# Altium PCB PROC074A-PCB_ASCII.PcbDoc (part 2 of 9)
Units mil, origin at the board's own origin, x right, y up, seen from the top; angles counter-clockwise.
Board outline 2755.91 x 5300 mil, 10 copper layers (Top Layer, L2-GND, L3-SIG1, L4-GND, L5-PWR/SIG, L6-SIG2, L7-PWR2, L8-SIG3, L9-GND, Bottom Layer), stack 67.57 mil thick; 586 components, 490 nets, 2137 pads, 1150 vias.
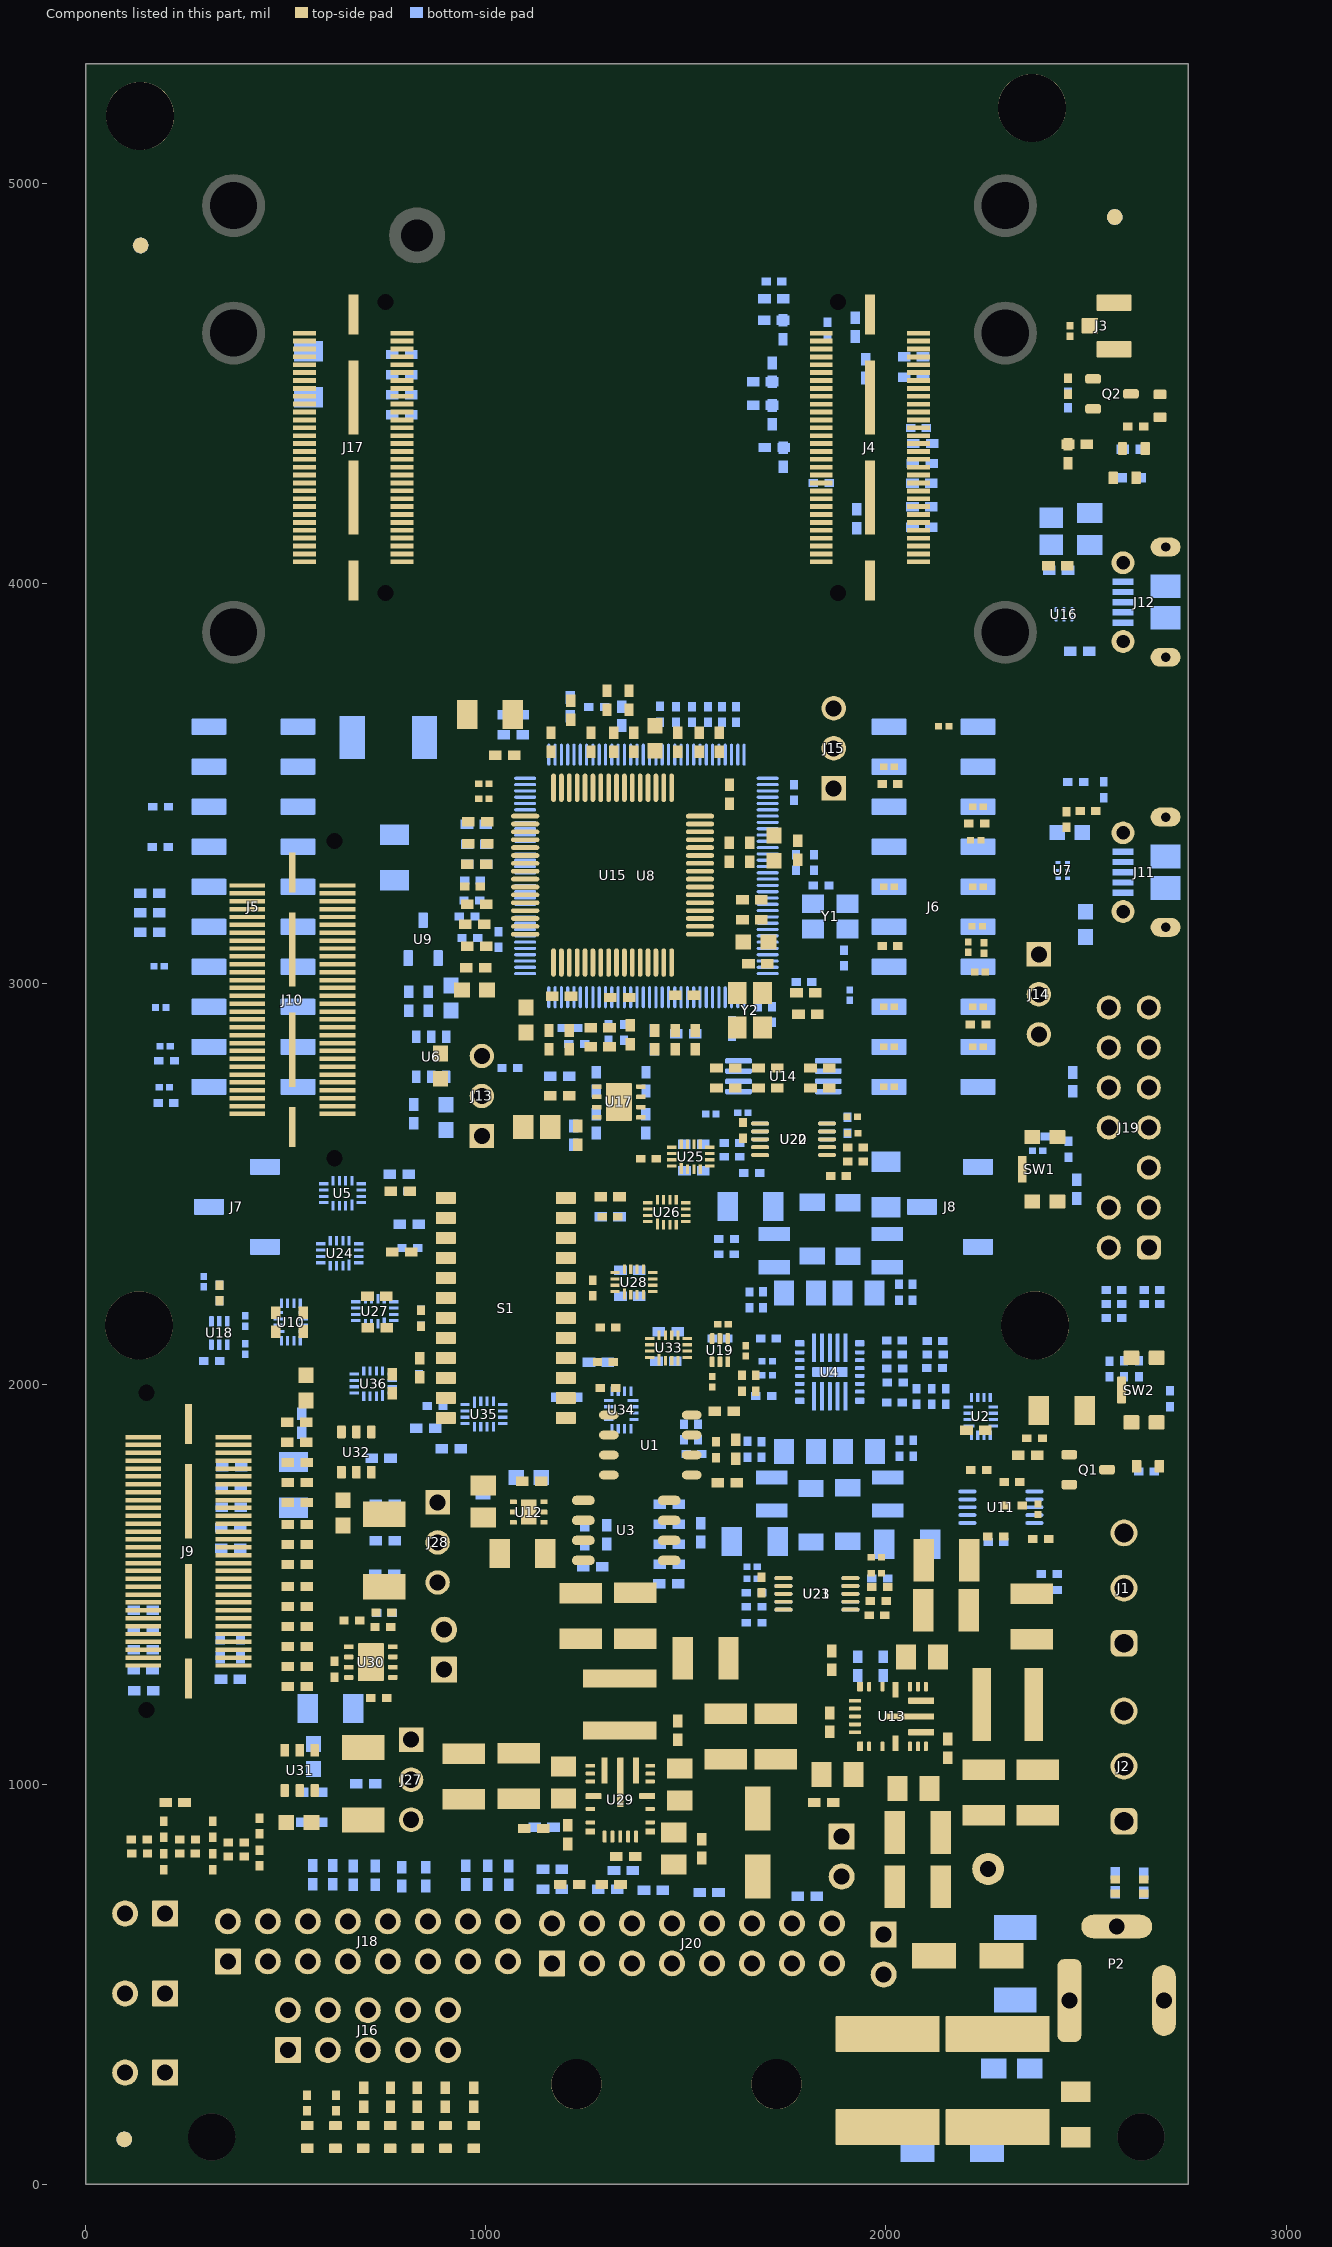
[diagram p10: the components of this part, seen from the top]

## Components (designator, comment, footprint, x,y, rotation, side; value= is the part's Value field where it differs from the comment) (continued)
R61 "CRCW040210K0FKED" 0402L 2010,3095 r0 top
R62 "CRCW04024K70JNED" 0402 1455.59,2130.24 r180 bottom
R63 "CRCW04024K70JNED" 0402 808.26,2399.95 r180 bottom
R64 "CRCW0402100KFKED" 0402L 2227,3401 r180 top
R65 "CRCW04024K70JNED" 0402 1201.75,1967.06 r0 bottom
R66 "CRCW04024K70JNED" 0402 1519.93,2599.87 r180 bottom
R67 "CRCW02010000Z0ED" 0201_Silk 2144.37,3644.06 r180 top
R68 "CRCW04024K70JNED" 0402 913.37,1838.06 r0 bottom
R69 "CRCW040210K0FKED" 0402 2090.01,4141.99 r180 bottom
R70 "CRCW02010000Z0ED" 0201_Silk 2007.63,3543 r0 top
R71 "CRCW040210K0FKED" 0402L 2570,2235 r0 bottom
R72 "CRCW02010000Z0ED" 0201_Silk 2230.07,3443 r0 top
R73 "CRCW0402100KFKED" 0402L 1720.37,4756.06 r180 bottom
R74 "ERJ-2GE0R00X" 0402L 2665,2200 r0 bottom
R75 "ERJ-2GE0R00X" 0402 160,3227 r180 bottom
R76 "CRCW02010000Z0ED" 0201_Silk 2224.37,3359.06 r0 top
R77 "CRCW02010000Z0ED" 0201_Silk 183.36,3044.06 r0 bottom
R78 "CRCW02010000Z0ED" 0201_Silk 2230.07,3243 r180 top
R79 "CRCW02010000Z0ED" 0201_Silk 187.38,2941.06 r0 bottom
R80 "ERJ-2GE0R00X" 0402L 2570,2200 r180 bottom
R81 "CRCW02010000Z0ED" 0201_Silk 2007.63,3243 r180 top
R82 "CRCW02010000Z0ED" 0201_Silk 198.37,2844.06 r0 bottom
R85 "CRCW02010000Z0ED" 0201_Silk 2228.36,3144.06 r180 top
R86 "CRCW02010000Z0ED" 0201_Silk 196.37,2742.06 r0 bottom
R88 "CRCW02010000Z0ED" 0201_Silk 1909.37,2972.05 r90 bottom
R89 "CRCW02010000Z0ED" 0201_Silk 2235,3030 r0 top
R90 "CRCW02010000Z0ED" 0201_Silk 2007.63,2943 r0 top
R91 "CRCW02010000Z0ED" 0201_Silk 2230.07,2943 r0 top
R92 "CRCW02010000Z0ED" 0201_Silk 2230.07,2843 r0 top
R93 "CRCW02010000Z0ED" 0201_Silk 2007.63,2843 r180 top
R94 "CRCW02010000Z0ED" 0201_Silk 2007.63,2743 r180 top
R95 "CRCW040210K0FKED" 0402L 2230.37,2899.06 r0 top
R96 "ERJ-2GE0R00X" 0402 362.62,1589.53 r180 bottom
R97 "CRCW04024K99FKED" 0402L 2021.27,2073.8 r0 bottom
R98 "CRCW04024K99FKED" 0402L 2023.27,2003.8 r0 bottom
R99 "CRCW02010000Z0ED" 0201_Silk 1703.26,2056.8 r180 bottom
R100 "CRCW02010000Z0ED" 0201_Silk 1703.26,2021.8 r180 bottom
R101 "CRCW04023R83FKED" 0402L 1692.69,2210.88 r90 bottom
R102 "CRCW04023R83FKED" 0402L 2032.22,2229.46 r90 bottom
R103 "CRCW04023R83FKED" 0402L 1689.22,1836.46 r270 bottom
R104 "CRCW04023R83FKED" 0402L 2034.22,1839.46 r270 bottom
R105 "ERJ-2GEJ102X" 0402L 2114.37,1969.06 r270 bottom
R106 "ERJ-2GE0R00X" 0402L 1601.72,2362.46 r0 bottom
R107 "ERJ-2RKF4991X" 0402L 2076.27,1968.8 r270 bottom
R108 "ERJ-2RKF4991X" 0402L 2123.37,2074.06 r180 bottom
R109 "CRCW040210K0FKED" 0402L 2149.37,1969.06 r90 bottom
R110 "CRCW040210K0FKED" 0402L 2121.68,2040.46 r180 bottom
R111 "CRCW0402100KFKED" 0402L 1601.41,2324.46 r0 bottom
R112 "CRCW04021K96FKED" 0402L 2122.37,2108.06 r180 bottom
R113 "CRCW20100000Z0EF" 2010 746.37,1584.06 r270 top
R114 "ERJ-2GEJ511X" 0402L 2651.37,1781.06 r180 bottom
R115 "CRCW20100000Z0EF" 2010 693,1001 r270 top
R116 "CRCW20100000Z0EF" 2010 2323,551 r90 bottom
R117 "ERJ-2GEJ511X" 0402L 2371.62,1864.53 r0 top
R118 "ERJ-2GEJ511X" 0402L 2624.37,4393.06 r180 top
R119 "ERJ-2GEJ101X" 0402L 2456,2587 r270 bottom
R120 "CRCW040210K0FKED" 0402L 2632.37,2038.06 r270 bottom
R121 "CRCW02010000Z0ED" 0201_Silk 2378.99,2583 r180 bottom
R122 "PMR18EZPFV2L00" 1206 1010.3,3673.44 r180 top
R123 "ERJ-2GEJ361X" 0402L 625.37,202.9 r90 top
R124 "ERJ-2GEJ101X" 0402L 2570,2165 r0 bottom
R125 "ERJ-2GEJ511X" 0402L 553,202.9 r90 top
R126 "CRCW040210K0FKED" 0402L 2379,2619 r0 bottom
R127 "ERJ-2GEJ101X" 0402L 2559,2037.68 r90 bottom
R128 "ERJ-2GEJ511X" 0402L 2455.37,4494.06 r90 top
R129 "ERJ-2GEJ101X" 0402L 2710,1963 r90 bottom
R130 "CRCW0402100KFKED" 0402L 2455,4460 r90 bottom
R131 "ERJ-2GE0R00X" 0402 223.06,954.08 r0 top
R132 "CRCW0402750RFKED" 0402L 134.54,826.26 r180 top
R133 "CRCW040210K0FKED" 0402L 194.68,887.05 r270 top
R134 "CRCW04027K87FKED" 0402L 194.68,805.99 r270 top
R135 "CRCW040282K5FKED" 0402L 133.54,861.27 r0 top
R136 "CRCW0402750RFKED" 0402L 254.54,861.27 r180 top
R137 "CRCW040210K0FKED" 0402L 254.37,826.26 r0 top
R138 "CRCW04027K87FKED" 0402L 317.18,805.99 r270 top
R139 "CRCW040282K5FKED" 0402L 317.18,887.05 r270 top
R140 "CRCW0402750RFKED" 0402L 434.59,895.45 r90 top
R141 "CRCW040210K0FKED" 0402L 375.81,853.64 r0 top
R142 "CRCW04027K87FKED" 0402L 434.59,815.45 r270 top
R143 "CRCW040282K5FKED" 0402L 375.81,818.64 r0 top
R144 "ERJ-2GE0R00X" 0402 527,1855 r180 top
R145 "ERJ-2GE0R00X" 0402 362.62,1640.53 r180 bottom locked
R146 "ERJ-2GE0R00X" 0402 363.87,1691.53 r180 bottom
R147 "RCS06030000Z0EA" 0603 886.91,2794.85 r90 top
R148 "CRCW0402510RJNED" 0402 856.1,2956.8 r270 bottom
R149 "ERJ-2RKF1003X" 0402 820,2675 r90 bottom
R150 "ERJ-2GE0R00X" 0402L 1059.92,2789.93 r180 bottom
R151 "CRCW040210K0FKED" 0402L 1406.35,2563.13 r180 top
R152 "CRCW0402330KFKED" 0402L 2451.11,3410.87 r270 top
R153 "CRCW040230K0FKED" 0402L 2544.37,3485.6 r270 bottom
R154 "MCT06030Z0000ZP500" 0603 2459.37,3378.62 r180 bottom
R155 "CRCW0402330KFKED" 0402L 2474.37,3505.06 r180 bottom
R156 "MCT06030Z0000ZP500" 0603 2498.62,3149.06 r90 bottom
R157 "ERJ-2GE0R00X" 0402 1068.37,3623.06 r0 bottom
R158 "ERJ-2GE0R00X" 0402L 1795,3005 r0 bottom
R159 "ERJ-2GEJ101X" 0402L 1680.49,2923.76 r270 bottom
R160 "ERJ-2GE0R00X" 0402 1068.37,3673.06 r0 bottom
R161 "CRCW02010000Z0ED" 0201_Silk 995,3463 r0 top
R162 "CRCW02010000Z0ED" 0201_Silk 995,3500 r0 top
R163 "CRCW04021K00FKED" 0402L 1625.49,3673.76 r90 bottom
R164 "CRCW04021K00FKED" 0402L 1590.49,3673.76 r90 bottom
R165 "CRCW04021K00FKED" 0402L 1555.49,3673.76 r90 bottom
R166 "CRCW04021K00FKED" 0402L 1515.49,3673.76 r90 bottom
R167 "CRCW040249R9FKED" 0402L 1227.37,2850.06 r0 bottom
R168 "CRCW040210K0FKED" 0402L 966.8,3258.99 r0 bottom
R169 "CRCW04021K00FKED" 0402L 965,3209 r0 bottom
R170 "CRCW04024K87FKED" 0402L 1475.49,3673.76 r270 bottom
R171 "CRCW02010000Z0ED" 0201_Silk 398.74,2087.66 r90 bottom
R172 "CRCW02010000Z0ED" 0201_Silk 1565.39,2005.62 r90 top
R173 "CRCW02010000Z0ED" 0201_Silk 1592.68,2149.37 r0 top
R174 "CRCW02010000Z0ED" 0201_Silk 398.74,2157.66 r90 bottom
R175 "CRCW02010000Z0ED" 0201_Silk 1650,2082.99 r90 top
R176 "CRCW040210K0FKED" 0402L 314.69,2057.58 r180 bottom
R177 "CRCW040210K0FKED" 0402L 1585.08,2113.82 r180 bottom
R178 "CRCW02010000Z0ED" 0201_Silk 294.37,2256.06 r90 bottom
R179 "ERJ-2GE0R00X" 0402L 334.43,2227.8 r90 bottom
R180 "ERJ-2GE0R00X" 0402L 1674.58,2002.2 r270 top
R181 "ERJ-2GE0R00X" 0402 1835,2740 r180 top
R182 "CRCW040233R2FKED" 0402 1582.78,3604.18 r90 top
R183 "CRCW040233R2FKED" 0402 1532.78,3604.18 r90 top
R184 "ERJ-2GE0R00X" 0402 1479.59,3604.18 r90 top
R185 "CRCW040210K0FKED" 0402 1600,2740 r180 top
R186 "CRCW040210K0FKED" 0402 1705,2740 r0 top
R187 "CRCW040210K0FKED" 0402 1600,2790 r180 top
R188 "CRCW040233R2FKED" 0402 1339.85,3669.59 r90 bottom
R189 "CRCW040210K0FKED" 0402 1357.78,3709.18 r90 top
R190 "CRCW040210K0FKED" 0402 1302.78,3709.18 r90 top
R191 "ERJ-2GEJ511X" 0402 2610.37,4265.06 r0 bottom
R192 "ERJ-2GE0R00X" 0402 1262.78,3604.18 r90 top
R193 "CRCW04022K20JNED" 0402 1705,2790 r0 top
R194 "ERJ-2GE0R00X" 0402 1369.78,3604.18 r90 top
R195 "ERJ-2GE0R00X" 0402 1319.78,3604.18 r90 top
R196 "ERJ-2GE0R00X" 0402 1212.37,3684.06 r90 top
R197 "CRCW040233R2FKED" 0402 1210.49,3692.39 r90 bottom
R198 "ERJ-2GE0R00X" 0402 1047.5,3572.06 r180 top
R199 "ERJ-2GE0R00X" 0402 980,3405 r180 top
R200 "ERJ-2GE0R00X" 0402 976.85,3299.15 r180 top
R201 "CRCW040210K0FKED" 0402 1665,3210 r180 top
R202 "ERJ-2GE0R00X" 0402 976.37,3399.06 r180 bottom
R203 "CRCW040210K0FKED" 0402L 810,2340 r180 bottom
R204 "ERJ-2GEJ102X" 0402 1609,3474 r270 top
R205 "ERJ-2GE0R00X" 0402 976.85,3299.15 r180 bottom
R206 "CRCW040233R2FKED" 0402 976.85,3199.15 r180 top
R207 "ERJ-2GE0R00X" 0402 971.85,3149.15 r180 top
R208 "CRCW040233R2FKED" 0402 976.85,3094.15 r180 top
R209 "CRCW040210K0FKED" 0402L 1310.37,2418.06 r180 top
R210 "ERJ-2GE0R00X" 0402 1157.78,2860.18 r270 top
R211 "ERJ-2GE0R00X" 0402 1207.93,2860.18 r270 top
R212 "CRCW040233R2FKED" 0402 1285.37,2843.06 r0 top
R213 "CRCW040233R2FKED" 0402 1285.37,2891.06 r0 top
R214 "CRCW040233R2FKED" 0402 1360.37,2873.06 r270 top
R215 "ERJ-2GE0R00X" 0402 1421.93,2860.18 r270 top
R216 "ERJ-2GE0R00X" 0402 1472.93,2860.18 r270 top
R217 "ERJ-2GE0R00X" 0402 1523.37,2860.06 r270 top
R218 "CRCW040233R2FKED" 0402 980,3350 r180 top
R219 "CRCW08050000Z0EA" 0805_HV 2509.37,4137.06 r90 bottom
R220 "CRCW08050000Z0EA" 0805 2413.01,4131.86 r90 bottom
R221 "CRCW08050000Z0EA" 0805 1127.09,2642.53 r180 top
R222 "CRCW040249K9FKED" 0402 1220,2621.38 r90 bottom
R223 "CRCW040230K0FKED" 0402 2430,4045 r0 top
R224 "ERJ-2GE0R00X" 0402 160,3178 r180 bottom
R225 "CRCW040229K4FKED" 0402 1400,2651.19 r90 bottom
R226 "CRCW0402100KFKED" 0402 1184.75,2769.06 r0 bottom
R227 "ERJ-2GE0R00X" 0402 2484.37,3832.06 r0 bottom
R228 "CRCW0402100KFKED" 0402 1275.51,2756.19 r270 bottom
R229 "ERJ-2GE0R00X" 0402 527.62,1904.53 r180 top
R230 "ERJ-2GE0R00X" 0402 363.62,1742.53 r180 bottom
R231 "ERJ-2GE0R00X" 0402 364.62,1793.53 r180 bottom
R232 "PMR18EZPFV2L00" 1206 556.77,4524.06 r270 bottom
R233 "ERJ-2GE0R00X" 0402 1209.37,749.06 r0 top
R234 "ERJ-2GE0R00X" 0402 1166.37,787.06 r180 bottom
R235 "PMR18EZPFV2L00" 1206 771.37,3316.06 r90 bottom
R236 "ERJ-2GE0R00X" 0402 335.62,1340.53 r90 bottom
R237 "ERJ-2GE0R00X" 0402 144.62,1233.53 r180 bottom
R238 "ERJ-2GE0R00X" 0402 386.62,1340.53 r90 bottom
R239 "ERJ-2GE0R00X" 0402 143,1286 r0 bottom
R240 "ERJ-2GE0R00X" 0402 1926.63,4163 r270 bottom
R241 "CRCW04024K70JNED" 0402 143.57,1335.99 r0 bottom
R242 "ERJ-2GEJ101X" 0402 361.62,1262.53 r0 bottom
R243 "CRCW04024K70JNED" 0402 528.26,1243.95 r0 top
R244 "CRCW04024K70JNED" 0402 143.62,1384.53 r0 bottom
R245 "ERJ-2GEJ101X" 0402 143.57,1434.42 r0 bottom
R246 "ERJ-2GE0R00X" 0402 528.26,1293.95 r180 top
R247 "CRCW0402100KFKED" 0402L 1854.01,4633.99 r90 bottom
R248 "CRCW0402100KFKED" 0402L 2081.5,4390.15 r180 bottom
R249 "CRCW0402100KFKED" 0402L 1838.5,4252.35 r0 bottom
R250 "CRCW040210K0FKED" 0402L 837.37,2164.37 r90 bottom
R251 "ERJ-2GEJ511X" 0402 829,217 r270 top
R252 "ERJ-2GEJ511X" 0402 898,217 r270 top
R253 "ERJ-2GEJ511X" 0402 969.5,217 r270 top
R254 "CRCW04021K60JNED" 0402 2615.37,4337.06 r180 bottom
R255 "CRCW0402750RFKED" 0402 694.26,217 r90 top
R256 "CRCW12060000Z0EA" 1206 1091.37,1576.06 r180 top
R260 "CRCW040210K0FKED" 0402L 2231.75,1785.05 r0 top
R261 "CRCW04024K70JNED" 0402 2354.3,1822.5 r180 top
R262 "CRCW04024K70JNED" 0402 1360,2285 r180 bottom
R268 "ERJ-2GE0R00X" 0402 528.26,1648.95 r180 top
R269 "ERJ-2GE0R00X" 0402 528.26,1703.95 r180 top
R270 "ERJ-2GE0R00X" 0402 528.26,1753.95 r180 top
R271 "CRCW040210K0JNED" 0402 1864.37,1309.06 r90 top
R272 "CRCW040210K0JNED" 0402 1844.37,954.06 r180 top
R273 "ERJ-2GE0R00X" 0402 1312.99,749.06 r0 top
R274 "CRCW040210K0FKED" 0402 2069.01,4567.99 r180 bottom
R275 "CRCW040210K0FKED" 0402 1720.01,4712.99 r180 bottom
R276 "ERJ-2GE0R00X" 0402 160,3129 r180 bottom
R281 "ERJ-2GE0R00X" 0402 2090.63,4301 r0 bottom
R283 "ERJ-2GE0R00X" 0402 2091.63,4351 r0 bottom
R286 "PMR18EZPFV2L00" 1206 2053.22,1599.46 r0 bottom
R287 "PMR18EZPFV2L00" 1206 2000.26,2498.95 r90 bottom
R288 "PMR18EZPFV2L00" 1206 1672.09,1606.1 r180 bottom
R289 "PMR18EZPFV2L00" 1206 1661.27,2443.8 r180 bottom
R290 "ERJ-2GE0R00X" 0402 1400.28,2756.19 r90 bottom
R291 "PMR18EZPFV2L00" 1206 2439.37,1934.06 r0 top
R293 "CRCW0402220RJNED" 0402 2644.37,752.06 r90 bottom
R294 "ERJ-2GE0R00X" 0402 1304.99,736.85 r180 bottom
R295 "ERJ-2GE0R00X" 0402 1418.96,734.82 r0 bottom
R296 "ERJ-2GE0R00X" 0402 1343.78,784.06 r180 bottom
R297 "ERJ-2GE0R00X" 0402 1803.48,719.8 r0 bottom
R298 "ERJ-2GE0R00X" 0402 1557.85,729.06 r180 bottom
R299 "CRCW040210K0FKED" 0402L 2274.37,1619.06 r180 top
R301 "CRCW040210K0FKED" 0402L 1881.37,2520.06 r180 top
R303 "CRCW02010000Z0ED" 0201 2380,1687.01 r90 top
R304 "CRCW02010000Z0ED" 0201 1915.91,2668.35 r0 top
R305 "CRCW02010000Z0ED" 0201 2206.38,1566.69 r180 bottom
R306 "CRCW02010000Z0ED" 0201 1917.09,2627.01 r0 top
R307 "CRCW040210K0FKED" 0402L 2315,1755 r0 top
R308 "CRCW040210K0FKED" 0402L 2320.82,1696.33 r0 top
R309 "CRCW040210K0JNED" 0402 1145.37,892.06 r180 bottom
R310 "CRCW040210K0FKED" 0402L 1924.09,2591.69 r180 top
R311 "CRCW040210K0FKED" 0402L 1924.09,2556.69 r180 top
R312 "CRCW040210K0JNED" 0402 1539.37,839.06 r270 top
R313 "CRCW0402280RFKED" 0402 2572.7,753.21 r90 bottom
R314 "CRCW040210K0FKED" 0402L 1670.44,1443.27 r180 bottom
R315 "CRCW040210K0JNED" 0402 1119.37,889.06 r180 top
R316 "CRCW040210K0FKED" 0402L 1615.37,2568.06 r180 bottom
R317 "CRCW040210K0FKED" 0402L 1980.62,1457.53 r0 top
R318 "CRCW040210K0JNED" 0402 1204.37,874.06 r90 top
R319 "CRCW02010000Z0ED" 0201 1665.44,1543.27 r180 bottom
R320 "CRCW02010000Z0ED" 0201 1642.37,2678.06 r180 bottom
R321 "CRCW02010000Z0ED" 0201 1976.1,1566.69 r0 top
R322 "CRCW02010000Z0ED" 0201 1665.44,1513.27 r180 bottom
R323 "CRCW02010000Z0ED" 0201 1562.37,2675.06 r180 bottom
R324 "CRCW02010000Z0ED" 0201 1976.1,1526.69 r0 top
R325 "CRCW040210K0FKED" 0402L 1670.44,1478.27 r0 bottom
R326 "CRCW0402510RJNED" 0402 564.7,904.23 r180 bottom
R327 "CRCW040210K0FKED" 0402L 1670.44,1403.27 r0 bottom
R328 "CRCW040210K0FKED" 0402L 1615.37,2602.06 r0 bottom
R329 "ERJ-2GEJ101X" 0402 690.62,1096.53 r180 bottom
R330 "CRCW040210K0FKED" 0402L 1664.37,2527.06 r180 bottom
R331 "CRCW040210K0FKED" 0402L 1984.37,1493.06 r180 top
R332 "CRCW040210K0FKED" 0402L 1977.55,1422.07 r180 top
R338 "CRCW04024K70JNED" 0402 1310.37,2468.06 r0 top
R339 "CRCW04024K70JNED" 0402 727.75,2219.06 r0 top
R346 "ERJ-2GE0R00X" 0402 2090.01,4193.05 r0 bottom
R347 "ERJ-2GE0R00X" 0402 1691.63,4505 r180 bottom
R348 "ERJ-2GE0R00X" 0402 2090.01,4251.03 r0 bottom
R349 "ERJ-2GE0R00X" 0402 1715.25,4528.62 r90 bottom
R350 "ERJ-2GE0R00X" 0402 2455.01,4325.24 r270 top
R351 "ERJ-2GE0R00X" 0402 2478.63,4348.87 r0 top
R353 "ERJ-2GE0R00X" 0402 790,4573.35 r0 bottom
R354 "ERJ-2GE0R00X" 0402 790,4523.35 r0 bottom
R356 "ERJ-2GE0R00X" 0402 790,4473.35 r0 bottom
R357 "ERJ-2GE0R00X" 0402 1719.01,4658.99 r180 bottom
R358 "ERJ-2GE0R00X" 0402 1742.63,4635.37 r270 bottom
R359 "ERJ-2GE0R00X" 0402 1691.63,4445.99 r180 bottom
R360 "ERJ-2GE0R00X" 0402 1715.25,4422.37 r270 bottom
R361 "ERJ-2GE0R00X" 0402 1743.25,4316.38 r270 bottom
R362 "ERJ-2GE0R00X" 0402 1720.63,4341 r180 bottom
R363 "CRCW0402510RJNED" 0402 539.37,1902.06 r270 bottom
R364 "CRCW040210K0FKED" 0402 699.38,1001 r0 bottom
R367 "ERJ-2GEJ101X" 0402 694.38,911 r0 bottom
R368 "ERJ-2GEJ101X" 0402 748.37,1699.06 r180 bottom
R369 "CRCW040210K0FKED" 0402 748.75,1608.06 r0 bottom
R370 "ERJ-2GEJ101X" 0402 747.37,1525.06 r0 bottom
R393 "CRCW02010000Z0ED" 0201_Silk 2245,3090 r270 top
R394 "CRCW02010000Z0ED" 0201_Silk 2206,3092.01 r90 top
R395 "CRCW040210K0FKED" 0402L 621.37,1287.06 r270 top
R396 "CRCW040214K0FKED" 0402L 745.05,1429.01 r0 top
R397 "PNM0402E3502BST1" 0402L 665.05,1409.01 r0 top
R398 "ERJ-2GE0R00X" 0402 790,4423.35 r0 bottom
R399 "CRCW040210K0FKED" 0402L 2021.27,1953.8 r180 bottom
R400 "CRCW040210K0FKED" 0402L 1706.27,2113.8 r0 bottom
R401 "CRCW040210K0FKED" 0402L 2021.27,2108.8 r180 bottom
R402 "CRCW040210K0FKED" 0402L 1694.37,1970.06 r0 bottom
R403 "CRCW040210K0JNED" 0402 1993.37,1295.06 r90 bottom
R404 "CRCW040210K0JNED" 0402 1929.37,1295.06 r270 bottom
S1 "218-12LPST" SW_218-12LPST 1050,2190 r180 top
SW1 "KMR243GLFG" SW_KMR243GLFG 2397,2537 r90 top
SW2 "KMR243GLFG" SW_KMR243GLFG 2645,1985 r90 top
TP1 "5001" Keystone5001 2255.37,788.06 r90 top
U1 "TCAN1042HGVDQ1" D0008A_L 1410.94,1847.63 r180 top
U2 "TS3A5018RSVR" RSV0016A 2237.16,1919.11 r0 bottom
U3 "SN65HVDA540QDR" D0008A_N 1350.88,1634.28 r0 top
U4 "LP87524JRNFRQ1" RNF0026C 1859.65,2030.1 r0 bottom locked
U5 "TS3A5018RSVR" RSV0016A 641.63,2477 r90 bottom
U6 "TPS22917DBVR" DBV0006A_L 863.38,2818.06 r90 bottom
U7 "TPD4E004DRYR" DRY0006A#1 2442,3284 r0 bottom
U8 "TM4C1294NCPDTT3" PDT0128A 1401.34,3269.99 r0 bottom
U9 "LM4040C25QDBZR" DBZ0003A_N 843.02,3112 r90 bottom
U10 "TS3A5018RSVR" RSV0016A 512.37,2155.06 r0 bottom
U11 "INA226AIDGST" DGS0010A_L 2287.37,1692.06 r180 bottom
U12 "TPS61240DRVR" DRV0006A 1106.98,1680.06 r180 top
U13 "LM536353QRNLRQ1" RNL0022A 2014.09,1169.06 r90 top
U14 "93LC46B-I/ST" TSSOP-8 1743.65,2769.42 r0 bottom
U15 "FT4232HL" LQFP64_N 1316.69,3271.95 r180 top
U16 "TPD4E004DRYR" DRY0006A#2 2445,3924 r90 bottom
U17 "TPS79601DRBR" DRB0008B#1 1332.36,2705 r0 top
U18 "TMP112AIDRLR" DRL0006A 333.74,2127.66 r90 bottom
U19 "TMP112AIDRLR" DRL0006A 1585.08,2084.69 r270 top
U20 "INA226AIDGST" DGS0010A_L 1769.09,2611.69 r180 top
U21 "INA226AIDGST" DGS0010A_L 1827.4,1475.47 r0 bottom
U22 "INA226AIDGST" DGS0010A_L 1769.09,2611.69 r0 bottom
U23 "INA226AIDGST" DGS0010A_L 1827.4,1475.47 r180 top
U24 "TS3A5018RSVR" RSV0016A 634.63,2326.95 r90 bottom
U25 "TS3A5018RSVR" RSV0016A 1512.06,2568.38 r90 top
U26 "TS3A5018RSVR" RSV0016A 1452.24,2429.55 r90 top
U27 "TS3A5018RSVR" RSV0016A 722.37,2182.06 r90 bottom
U28 "TS3A5018RSVR" RSV0016A 1370,2255 r90 top
U29 "LM536255QRNLRQ1" RNL0022A 1335.93,960.36 r180 top
U30 "TPS79601DRBR" DRB0008B#2 712.41,1305 r180 top
U31 "TPS22917DBVR" DBV0006A_L 534.7,1034.23 r270 top
U32 "TPS22917DBVR" DBV0006A_L 676.37,1830.06 r90 top
U33 "TS3A5018RSVR" RSV0016A 1456.59,2090.24 r90 top
U34 "TS3A5018RSVR" RSV0016A 1338.75,1935.3 r180 bottom
U35 "TS3A5018RSVR" RSV0016A 995,1925 r270 bottom
U36 "TS3A5018RSVR" RSV0016A 718.37,2001.06 r90 bottom
Y1 "NX3225SA-16.000M-STD-CRS-2" NDK_NX3225SA 1861,3169 r270 bottom
Y2 "NX3225SA-12.000M-STD-CRS-2" NDK_NX3225SA 1659.85,2934.59 r180 top
ZZ1 "This Assembly Note is for PCB labels only" AssemblyNoteLabel -628,5874 r0 top
ZZ2 "These assemblies are ESD sensitive, ESD precautions shall be observed." AssemblyNote -628,5765.11 r0 top
ZZ3 "These assemblies must be clean and free from flux and all contaminants. Use of no clean flux is not acceptable." AssemblyNote -628,5676.56 r0 top
ZZ4 "These assemblies must comply with workmanship standards IPC-A-610 Class 2, unless otherwise specified." AssemblyNote -628,5588 r0 top
ZZ5 "Refer SWRU546.pdf(section 2.3) for installing hardware" AssemblyNote -621.82,5505.34 r0 top

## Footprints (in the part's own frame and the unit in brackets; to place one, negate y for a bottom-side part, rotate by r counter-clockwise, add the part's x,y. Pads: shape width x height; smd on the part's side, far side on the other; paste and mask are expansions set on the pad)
0201 [mm] "Data from Kemet datasheet CC101_COM dated 7/28/11"
  rect 0.46x0.42 smd: 1(-0.33,0) 2(0.33,0)
0201_Silk [mm] "Data from Kemet datasheet CC101_COM dated 7/28/11"
  rect 0.46x0.42 smd: 1(-0.33,0) 2(0.33,0)
  silkscreen extent -0.75,-0.4 0.75,0.4
0402 [mm] "0402 from SM-752 data"
  rect 0.8x0.6 smd: 1(-0.6,0) 2(0.6,0)
  silkscreen extent -1.22,-0.52 1.22,0.52
0402_065 [mm] "0402"
  rect 0.8x0.6 smd: 1(-0.6,0) 2(0.6,0)
  silkscreen extent -1.22,-0.52 1.22,0.52
0402_065L [mm] "0402"
  rect 0.6x0.5 smd: 1(-0.5,0) 2(0.5,0)
0402L [mm] "0402 from SM-752 data"
  rect 0.6x0.5 smd: 1(-0.5,0) 2(0.5,0)
597D_Z [mm] "SMD, 2-Leads, Body 6.2x6mm"
  rrect4% 2.3x6.6 smd: 1(-2.95,0) 2(2.95,0)
0603 [mm] "0603 from SM-752 data"
  rect 1x0.95 smd: 1(-0.8,0) 2(0.8,0)
  silkscreen extent -1.52,-0.69 1.52,0.69
0805 [mm] "0805 from SM-752 data"
  rect 1.3x1.5 smd: 1(-0.85,0) 2(0.85,0)
  silkscreen extent -1.72,-0.97 1.72,0.97
0805_HV [mil] "0805 with 30mil clearance between pads"
  rect 50x63 smd: 1(-40,0) 2(40,0)
  silkscreen extent -74,-40 74,40
1206 [mm] "1206 from SM-752 data"
  rect 1.3x1.85 smd: 1(-1.45,0) 2(1.45,0)
  silkscreen extent -2.4,-1.21 2.4,1.21
1206_180 [mm] "1206_180"
  rect 1.1x1.6 smd: 1(-1.7,0) 2(1.7,0)
  silkscreen extent -0.9,-1 0.9,1
1210 [mm] "1210 from SM-752 data"
  rect 1.3x2.7 smd: 1(-1.45,0) 2(1.45,0)
  silkscreen extent -2.32,-1.57 2.32,1.57
1210_270 [mm] "1210"
  rect 1.3x2.7 smd: 1(-1.45,0) 2(1.45,0)
  silkscreen extent -2.32,-1.57 2.32,1.57
2010 [mm] "Chip Capacitor, Body 5.08x2.54mm, IPC Medium Density"
  rect 1.6x2.7 smd: 1(-2.3,0) 2(2.3,0)
  silkscreen extent -3.42,-1.65 3.42,1.65
AssemblyNote [mil] "Assembly Note"
AssemblyNoteLabel [mil] "Assembly Note for PCB Labels"
CE_Mark_5mm [mil] "Minimum text height for CE Mark"
CONN_105017-0001 [mm] "Molex Micro USB-B"
  rect 0.4x1.35 smd: 1(-1.3,1.35) 2(-0.65,1.35) 3(0,1.35) 4(0.65,1.35) 5(1.3,1.35)
  oval 1.2x1.9 hole 0.6 slot 1.3 at 90 deg: 6(-3.5,-1.35) 9(3.5,-1.35)
  rect 1.5x1.9 smd: 7(-1,-1.35) 8(1,-1.35)
  round 1.45 hole 0.85: 10(2.5,1.35) 11(-2.5,1.35)
  Top Layer region: -3.5,-0.4 -2.3,-0.4 -2.3,-2.3 -3.5,-2.3
  Top Layer region: 3.5,-2.3 2.3,-2.3 2.3,-0.4 3.5,-0.4
  silkscreen extent -4.1,-0.2 4.1,1.4
CUI_PJ-002AH [mm] "DC POWER JACK, R/A, TH"
  rrect50% 1.5x5.25 hole 1 square: 1(-3,0)
  oval 1.5x4.5 hole 1 square: 2(3,0)
  oval 4.5x1.5 hole 1 square: 3(0,4.7)
  silkscreen extent -4.1,-4.5 10.7,4.5
D0008A_L [mm] "SOIC, 8-Leads, Body 4.9x3.9mm, Pitch 1.27mm, IPC High Density"
  oval 1.25x0.55 smd: 1(-2.625,1.905) 2(-2.625,0.635) 3(-2.625,-0.635) 4(-2.625,-1.905) 5(2.625,-1.905) 6(2.625,-0.635) 7(2.625,0.635) 8(2.625,1.905)
  silkscreen extent -3.1,-2.5 0.9,2.5
D0008A_N [mm] "SOIC, 8-Leads, Body 4.9x3.9mm, Pitch 1.27mm, IPC Medium Density"
  oval 1.45x0.6 smd: 1(-2.725,1.905) 2(-2.725,0.635) 3(-2.725,-0.635) 4(-2.725,-1.905) 5(2.725,-1.905) 6(2.725,-0.635) 7(2.725,0.635) 8(2.725,1.905)
  silkscreen extent -3.3,-2.5 0.9,2.5
DBV0006A_L [mm] "SOT23, 6-Leads, Body 2.9x1.6mm, Pitch 0.95mm, Lead Span 2.8mm, IPC High Density"
  rrect18% 0.8x0.55 smd: 1(-1.275,0.95) 2(-1.275,0) 3(-1.275,-0.95) 4(1.275,-0.95) 5(1.275,0) 6(1.275,0.95)
  silkscreen extent -1.55,-1.53 0.55,1.53
DBZ0003A_N [mm] "SOT23, 3-Leads, Body 2.9x1.3mm, Pitch 0.95mm, Lead Span 2.4mm, IPC Medium Density"
  rrect17% 1x0.6 smd: 1(-1.2,0.95) 2(-1.2,-0.95) 3(1.2,0)
  silkscreen extent 0.2,-1.5 0.7,1.5
DFE252012P [mm] "TOKO, Pad sizes increased as per request"
  rect 0.9x2 smd: 1(-1.05,0) 2(1.05,0)
  silkscreen extent -0.3,-1.2 0.3,1.2
DGS0010A_L [mm] "TSSOP, 10-Leads, Body 3x3mm, Pitch 0.5mm, IPC High Density"
  oval 1.15x0.25 smd: 1(-2.125,1) 2(-2.125,0.5) 3(-2.125,0) 4(-2.125,-0.5) 5(-2.125,-1) 6(2.125,-1) 7(2.125,-0.5) 8(2.125,0) 9(2.125,0.5) 10(2.125,1)
  silkscreen extent -2.65,-1.55 0.9,1.55
DRB0008B#1 [mm] "SON, 8-Leads, Body 3x3mm, Pitch 0.65mm, Thermal Pad 2.4x1.65mm, TI Recommended"
  rrect33% 0.6x0.3 smd: 1(-1.4,0.975) 2(-1.4,0.325) 3(-1.4,-0.325) 4(-1.4,-0.975) 5(1.4,-0.975) 6(1.4,-0.325) 7(1.4,0.325) 8(1.4,0.975)
  rrect9% 1.47x1.06 on Top Paste: 9(0,-0.63) 9(0,0.63)
  rrect6% 1.65x2.4 smd paste-1.2: 9(0,0)
  silkscreen extent -1.73,-1.73 1.73,1.73
DRB0008B#2 [mm] "SON, 8-Leads, Body 3x3mm, Pitch 0.65mm, Thermal Pad 2.4x1.65mm, TI Recommended"
  rrect33% 0.6x0.3 smd: 1(-1.4,0.975) 2(-1.4,0.325) 3(-1.4,-0.325) 4(-1.4,-0.975) 5(1.4,-0.975) 6(1.4,-0.325) 7(1.4,0.325) 8(1.4,0.975)
  rrect6% 1.65x2.4 smd paste-1.2: 9(0,0)
  silkscreen extent -1.73,-1.73 1.73,1.73
DRL0006A [mm] "SOTFL, 6-Flat Leads, Body 1.2x1.6x0.6mm, Pitch 0.5mm, TI recommended"
  rrect33% 0.67x0.3 smd: 1(-0.74,0.5) 2(-0.74,0) 3(-0.74,-0.5) 4(0.74,-0.5) 5(0.74,0) 6(0.74,0.5)
  silkscreen extent -0.9,-0.95 0.5,0.95
DRV0006A [mm] "SON, 6-Leads, Body 2x2mm, Pitch 0.65mm, Thermal Pad 1.6x1mm, TI Recommended"
  rrect33% 0.45x0.3 smd: 1(-0.975,0.65) 2(-0.975,0) 3(-0.975,-0.65) 4(0.975,-0.65) 5(0.975,0) 6(0.975,0.65)
  rrect14% 1x0.7 on Top Paste: 7(0,0.45) 7(0,-0.45)
  rrect10% 1x1.6 smd paste-0.5: 7(0,0)
  silkscreen extent -1.05,-1.2 1.05,1.2
DRY0006A#1 [mm] "PSON, 6-Leads, Body 1x1.45mm, Pitch 0.5mm, TI Recommended"
  rect 0.35x0.2 smd: 1(-0.275,0.5)
  rect 0.3x0.2 smd: 2(-0.3,0) 3(-0.3,-0.5) 4(0.3,-0.5) 5(0.3,0) 6(0.3,0.5)
  silkscreen extent -0.5,-0.85 0.2,0.85
DRY0006A#2 [mm] "PSON, 6-Leads, Body 1x1.45mm, Pitch 0.5mm, TI Recommended"
  rrect50% 0.35x0.2 smd: 1(-0.275,0.5)
  rrect50% 0.3x0.2 smd: 2(-0.3,0) 3(-0.3,-0.5) 4(0.3,-0.5) 5(0.3,0) 6(0.3,0.5)
FCC_disclaimer [mil]
Fiducial10-20 [mm]
  round 1 smd mask+0: 1(0,0)
  Top Layer keep-out circle w1.178: c0,0 r0.5
IEC_HotSurface_Small [mil]
  silkscreen extent -107,-93 107,92
Johnson_128-0711-201 [mm] "UMC Straight Jack Receptacle, 50 Ohm, SMT"
  rrect10% 1x1.05 smd: 1(0,1.525)
  rrect10% 1.05x2.2 smd: 2(-1.475,0) 3(1.475,0)
  silkscreen extent -0.6,-1.3 0.6,-1.3
Keystone5001 [mil] "For Keystone 500x miniature loop terminals"
  round 80 hole 40: 1(0,0)
  silkscreen extent -52,-52 52,52
Label_650x200 [mil] "Thermal Transfer Label"
  round 1 on Mech13: 0(0,0)
  silkscreen extent -325,-100 325,100
LQFP64_N [mm] "Thin QFP, 64-Leads, Body 10x10mm, Pitch 0.5mm, IPC Medium Density"
  oval 1.8x0.3 smd: 1(-5.55,3.75) 2(-5.55,3.25) 3(-5.55,2.75) 4(-5.55,2.25) 5(-5.55,1.75) 6(-5.55,1.25) 7(-5.55,0.75) 8(-5.55,0.25) 9(-5.55,-0.25) 10(-5.55,-0.75) 11(-5.55,-1.25) 12(-5.55,-1.75) 13(-5.55,-2.25) 14(-5.55,-2.75) 15(-5.55,-3.25) 16(-5.55,-3.75) 33(5.55,-3.75) 34(5.55,-3.25) 35(5.55,-2.75) 36(5.55,-2.25) 37(5.55,-1.75) 38(5.55,-1.25) 39(5.55,-0.75) 40(5.55,-0.25) 41(5.55,0.25) 42(5.55,0.75) 43(5.55,1.25) 44(5.55,1.75) 45(5.55,2.25) 46(5.55,2.75) 47(5.55,3.25) 48(5.55,3.75)
  oval 0.3x1.8 smd: 17(-3.75,-5.55) 18(-3.25,-5.55) 19(-2.75,-5.55) 20(-2.25,-5.55) 21(-1.75,-5.55) 22(-1.25,-5.55) 23(-0.75,-5.55) 24(-0.25,-5.55) 25(0.25,-5.55) 26(0.75,-5.55) 27(1.25,-5.55) 28(1.75,-5.55) 29(2.25,-5.55) 30(2.75,-5.55) 31(3.25,-5.55) 32(3.75,-5.55) 49(3.75,5.55) 50(3.25,5.55) 51(2.75,5.55) 52(2.25,5.55) 53(1.75,5.55) 54(1.25,5.55) 55(0.75,5.55) 56(0.25,5.55) 57(-0.25,5.55) 58(-0.75,5.55) 59(-1.25,5.55) 60(-1.75,5.55) 61(-2.25,5.55) 62(-2.75,5.55) 63(-3.25,5.55) 64(-3.75,5.55)
  silkscreen extent -5.68,-4.25 4.25,4.57
Molex_0022284033 [mm] "Header, 2.54mm, 3x1, TH"
  rect 1.55x1.55 hole 1.02: 1(-2.54,0)
  round 1.55 hole 1.02: 2(0,0) 3(2.54,0)
  silkscreen extent -3.81,-1.24 3.81,1.5
MTGNP431H431 [mil] "MOUNTING HOLE, NON PLATED, 4.318MM DRILL"
  round 170 hole 170 unplated: ""(0,0)
  Keep-Out Layer circle w0.98: c0,0 r125
  silkscreen extent -97,-97 97,97
NDK_NX3225SA [mm] "NDK"
  rect 1.2x1.4 smd: 1(-0.8,1.1) 2(-0.8,-1.1) 3(0.8,-1.1) 4(0.8,1.1)
On-Shore_OSTTE030161 [mm] "Terminal Block, 3.5mm, 3x1, TH"
  rrect50% 1.7x1.7 hole 1.2: 1(-3.5,0)
  round 1.7 hole 1.2: 2(0,0) 3(3.5,0)
  silkscreen extent -5.25,-3.6 5.25,4.05
PDT0128A [mm] "Thin QFP, 128-Leads, Body 14x14mm, Pitch 0.4mm"
  oval 1.4x0.2 smd: 1(-7.7,6.2) 2(-7.7,5.8) 3(-7.7,5.4) 4(-7.7,5) 5(-7.7,4.6) 6(-7.7,4.2) 7(-7.7,3.8) 8(-7.7,3.4) 9(-7.7,3) 10(-7.7,2.6) 11(-7.7,2.2) 12(-7.7,1.8) 13(-7.7,1.4) 14(-7.7,1) 15(-7.7,0.6) 16(-7.7,0.2) 17(-7.7,-0.2) 18(-7.7,-0.6) 19(-7.7,-1) 20(-7.7,-1.4) 21(-7.7,-1.8) 22(-7.7,-2.2) 23(-7.7,-2.6) 24(-7.7,-3) 25(-7.7,-3.4) 26(-7.7,-3.8) 27(-7.7,-4.2) 28(-7.7,-4.6) 29(-7.7,-5) 30(-7.7,-5.4) 31(-7.7,-5.8) 32(-7.7,-6.2) 65(7.7,-6.2) 66(7.7,-5.8) 67(7.7,-5.4) 68(7.7,-5) 69(7.7,-4.6) 70(7.7,-4.2) 71(7.7,-3.8) 72(7.7,-3.4) 73(7.7,-3) 74(7.7,-2.6) 75(7.7,-2.2) 76(7.7,-1.8) 77(7.7,-1.4) 78(7.7,-1) 79(7.7,-0.6) 80(7.7,-0.2) 81(7.7,0.2) 82(7.7,0.6) 83(7.7,1) 84(7.7,1.4) 85(7.7,1.8) 86(7.7,2.2) 87(7.7,2.6) 88(7.7,3) 89(7.7,3.4) 90(7.7,3.8) 91(7.7,4.2) 92(7.7,4.6) 93(7.7,5) 94(7.7,5.4) 95(7.7,5.8) 96(7.7,6.2)
  oval 0.2x1.4 smd: 33(-6.2,-7.7) 34(-5.8,-7.7) 35(-5.4,-7.7) 36(-5,-7.7) 37(-4.6,-7.7) 38(-4.2,-7.7) 39(-3.8,-7.7) 40(-3.4,-7.7) 41(-3,-7.7) 42(-2.6,-7.7) 43(-2.2,-7.7) 44(-1.8,-7.7) 45(-1.4,-7.7) 46(-1,-7.7) 47(-0.6,-7.7) 48(-0.2,-7.7) 49(0.2,-7.7) 50(0.6,-7.7) 51(1,-7.7) 52(1.4,-7.7) 53(1.8,-7.7) 54(2.2,-7.7) 55(2.6,-7.7) 56(3,-7.7) 57(3.4,-7.7) 58(3.8,-7.7) 59(4.2,-7.7) 60(4.6,-7.7) 61(5,-7.7) 62(5.4,-7.7) 63(5.8,-7.7) 64(6.2,-7.7) 97(6.2,7.7) 98(5.8,7.7) 99(5.4,7.7) 100(5,7.7) 101(4.6,7.7) 102(4.2,7.7) 103(3.8,7.7) 104(3.4,7.7) 105(3,7.7) 106(2.6,7.7) 107(2.2,7.7) 108(1.8,7.7) 109(1.4,7.7) 110(1,7.7) 111(0.6,7.7) 112(0.2,7.7) 113(-0.2,7.7) 114(-0.6,7.7) 115(-1,7.7) 116(-1.4,7.7) 117(-1.8,7.7) 118(-2.2,7.7) 119(-2.6,7.7) 120(-3,7.7) 121(-3.4,7.7) 122(-3.8,7.7) 123(-4.2,7.7) 124(-4.6,7.7) 125(-5,7.7) 126(-5.4,7.7) 127(-5.8,7.7) 128(-6.2,7.7)
  silkscreen extent -7.2,-6.3 6.3,6.99
RNF0026C [mm] "QFN, 26-Leads, Body 4x4.5mm, Pitch 0.5mm"
  rrect25% 0.6x0.4 smd paste-0.3: 1(-1.9,1.825) 8(-1.9,-1.825) 14(1.9,-1.825) 21(1.9,1.825)
  rrect40% 0.6x0.25 smd paste+0: 2(-1.9,1.25) 3(-1.9,0.75) 4(-1.9,0.25) 5(-1.9,-0.25) 6(-1.9,-0.75) 7(-1.9,-1.25) 15(1.9,-1.25) 16(1.9,-0.75) 17(1.9,-0.25) 18(1.9,0.25) 19(1.9,0.75) 20(1.9,1.25)
  rrect40% 0.25x1.82 smd paste-1: 9(-1,-1.54) 10(-0.5,-1.54) 11(0,-1.54) 12(0.5,-1.54) 13(1,-1.54) 22(1,1.54) 23(0.5,1.54) 24(0,1.54) 25(-0.5,1.54) 26(-1,1.54)
  rrect15% 2.24x0.66 smd paste-1: 27(0,0)
  rrect33% 0.6x0.3 on Bottom Paste: ""(-1.9,-1.775) ""(-1.9,1.775) ""(1.9,-1.775) ""(1.9,1.775)
  rrect33% 0.3x0.825 on Bottom Paste: ""(-1.575,-2.037) ""(-1.575,2.037) ""(1.575,-2.037) ""(1.575,2.037)
  rrect40% 0.25x0.81 on Bottom Paste: ""(-1,-2.045) ""(-1,-1.035) ""(-1,1.035) ""(-1,2.045) ""(-0.5,-2.045) ""(-0.5,-1.035) ""(-0.5,1.035) ""(-0.5,2.045) ""(0,-2.045) ""(0,-1.035) ""(0,1.035) ""(0,2.045) ""(0.5,-2.045) ""(0.5,-1.035) ""(0.5,1.035) ""(0.5,2.045) ""(1,-2.045) ""(1,-1.035) ""(1,1.035) ""(1,2.045)
  rrect15% 0.98x0.66 on Bottom Paste: ""(-0.59,0) ""(0.59,0)
  silkscreen extent -2.45,-2.7 2.45,2.7
RNL0022A [mm] "VQFN-HR-22"
  rrect25% 0.6x0.4 smd: 1(-1.9,2) 17(1.9,2)
  rrect40% 0.6x0.25 smd: 2(-1.9,1.425) 3(-1.9,0.575) 5(-1.9,-1.175) 6(-1.9,-1.675) 7(-1.9,-2.175) 11(1.9,-2.175) 12(1.9,-1.675) 13(1.9,-1.175) 15(1.9,0.575) 16(1.9,1.425)
  rrect25% 1x0.4 smd paste-0.25: 4(-1.7,-0.25) 14(1.7,-0.25)
  rrect25% 0.4x0.4 on Top Paste: 4A(-2,-0.25) 4B(-1.4,-0.25) 14A(1.4,-0.25) 14B(2,-0.25)
  rrect25% 0.4x1.65 smd paste-0.25: 8(-1,-1.875) 10(1,-1.875)
  rrect25% 0.4x0.66 on Top Paste: 8A(-1,-1.445) 8B(-1,-2.305) 10A(1,-1.445) 10B(1,-2.305)
  rrect25% 0.4x3.15 smd paste-0.25: 9(0,-1.125)
  rrect25% 0.4x0.63 on Top Paste: 9A(0,0.12) 9B(0,-0.71) 9C(0,-1.54) 9D(0,-2.37)
  rrect40% 0.25x0.75 smd: 18(1,2.325) 19(0.5,2.325) 20(0,2.325) 21(-0.5,2.325) 22(-1,2.325)
RSV0016A [mm] "QFN, 16-Leads, Body 1.8x2.6mm, Pitch 0.4mm, TI Recommended"
  rect 0.7x0.2 smd: 1(-0.75,0.6)
  rect 0.6x0.2 smd: 2(-0.8,0.2) 3(-0.8,-0.2) 4(-0.8,-0.6) 9(0.8,-0.6) 10(0.8,-0.2) 11(0.8,0.2) 12(0.8,0.6)
  rect 0.2x0.6 smd: 5(-0.6,-1.2) 6(-0.2,-1.2) 7(0.2,-1.2) 8(0.6,-1.2) 13(0.6,1.2) 14(0.2,1.2) 15(-0.2,1.2) 16(-0.6,1.2)
  silkscreen extent -1.08,-1.33 1.08,1.45
Samtec_QSH-030-01-X-D-A [mm] "Receptacle, 0.5 mm, 30x2, TH"
  rect 2.27x0.279 smd: 1(-2.865,7.25) 2(2.865,7.25) 3(-2.865,6.75) 4(2.865,6.75) 5(-2.865,6.25) 6(2.865,6.25) 7(-2.865,5.75) 8(2.865,5.75) 9(-2.865,5.25) 10(2.865,5.25) 11(-2.865,4.75) 12(2.865,4.75) 13(-2.865,4.25) 14(2.865,4.25) 15(-2.865,3.75) 16(2.865,3.75) 17(-2.865,3.25) 18(2.865,3.25) 19(-2.865,2.75) 20(2.865,2.75) 21(-2.865,2.25) 22(2.865,2.25) 23(-2.865,1.75) 24(2.865,1.75) 25(-2.865,1.25) 26(2.865,1.25) 27(-2.865,0.75) 28(2.865,0.75) 29(-2.865,0.25) 30(2.865,0.25) 31(-2.865,-0.25) 32(2.865,-0.25) 33(-2.865,-0.75) 34(2.865,-0.75) 35(-2.865,-1.25) 36(2.865,-1.25) 37(-2.865,-1.75) 38(2.865,-1.75) 39(-2.865,-2.25) 40(2.865,-2.25) 41(-2.865,-2.75) 42(2.865,-2.75) 43(-2.865,-3.25) 44(2.865,-3.25) 45(-2.865,-3.75) 46(2.865,-3.75) 47(-2.865,-4.25) 48(2.865,-4.25) 49(-2.865,-4.75) 50(2.865,-4.75) 51(-2.865,-5.25) 52(2.865,-5.25) 53(-2.865,-5.75) 54(2.865,-5.75) 55(-2.865,-6.25) 56(2.865,-6.25) 57(-2.865,-6.75) 58(2.865,-6.75) 59(-2.865,-7.25) 60(2.865,-7.25)
  round 0 hole 1.02 unplated mask+0: MH1(2.67,10.065) MH2(2.67,-10.065)
  rect 0.43x2.54 smd: MP1(0,8.065) MP4(0,-8.065)
  rect 0.43x4.7 smd: MP2(0,3.175) MP3(0,-3.175)
  silkscreen extent -3.9,-10.66 3.62,10.66
Samtec_QTH-030-01-x-D-A [mil] "Header (Shrouded), 19.7mil, 30x2, SMT"
  rect 12x57 smd: 1(-285.7,121.5) 2(-285.7,-121.5) 3(-266,121.5) 4(-266,-121.5) 5(-246.3,121.5) 6(-246.3,-121.5) 7(-226.6,121.5) 8(-226.6,-121.5) 9(-206.9,121.5) 10(-206.9,-121.5) 11(-187.2,121.5) 12(-187.2,-121.5) 13(-167.5,121.5) 14(-167.5,-121.5) 15(-147.8,121.5) 16(-147.8,-121.5) 17(-128.1,121.5) 18(-128.1,-121.5) 19(-108.4,121.5) 20(-108.4,-121.5) 21(-88.7,121.5) 22(-88.7,-121.5) 23(-69,121.5) 24(-69,-121.5) 25(-49.3,121.5) 26(-49.3,-121.5) 27(-29.6,121.5) 28(-29.6,-121.5) 29(-9.9,121.5) 30(-9.9,-121.5) 31(9.8,121.5) 32(9.8,-121.5) 33(29.5,121.5) 34(29.5,-121.5) 35(49.2,121.5) 36(49.2,-121.5) 37(68.9,121.5) 38(68.9,-121.5) 39(88.6,121.5) 40(88.6,-121.5) 41(108.3,121.5) 42(108.3,-121.5) 43(128,121.5) 44(128,-121.5) 45(147.7,121.5) 46(147.7,-121.5) 47(167.4,121.5) 48(167.4,-121.5) 49(187.1,121.5) 50(187.1,-121.5) 51(206.8,121.5) 52(206.8,-121.5) 53(226.5,121.5) 54(226.5,-121.5) 55(246.2,121.5) 56(246.2,-121.5) 57(265.9,121.5) 58(265.9,-121.5) 59(285.6,121.5) 60(285.6,-121.5)
  round 28 hole 40 unplated mask+0: MH1(-364,80) MH2(364,80)
  rect 100x25 smd: MP1(-332.7,0) MP4(332.3,0)
  rect 185x25 smd: MP2(-125.2,0) MP3(124.8,0)
  silkscreen extent -394,-118 394,131
Samtec_SSM-103-x-SV [mm] "Receptacle, 2.54mm, 3x1, SMT"
  rrect10% 1.02x1.905 smd: 1(-2.54,-1.777) 2(0,1.777) 3(2.54,-1.777)
  silkscreen extent -3.81,-2.28 3.81,1.28
Samtec_SSM-110-x-DV [mm] "Receptacle, 2.54mm, 10x2, SMT"
  rrect10% 1.02x2.22 smd: 1(-11.43,2.825) 2(-11.43,-2.825) 3(-8.89,2.825) 4(-8.89,-2.825) 5(-6.35,2.825) 6(-6.35,-2.825) 7(-3.81,2.825) 8(-3.81,-2.825) 9(-1.27,2.825) 10(-1.27,-2.825) 11(1.27,2.825) 12(1.27,-2.825) 13(3.81,2.825) 14(3.81,-2.825) 15(6.35,2.825) 16(6.35,-2.825) 17(8.89,2.825) 18(8.89,-2.825) 19(11.43,2.825) 20(11.43,-2.825)
  silkscreen extent -13.02,-2.54 12.7,2.54
Samtec_TSW-107-07-L-D-006 [mm] "Header, 2.54mm, 13 Pos, TH"
  rrect50% 1.53x1.53 hole 1.02: 1(-1.27,7.62)
  round 1.53 hole 1.02: 2(1.27,7.62) 3(-1.27,5.08) 4(1.27,5.08) 5(-1.27,2.54) 7(-1.27,0) 8(1.27,0) 9(-1.27,-2.54) 10(1.27,-2.54) 11(-1.27,-5.08) 12(1.27,-5.08) 13(-1.27,-7.62) 14(1.27,-7.62)
SM_RADIAL_C [mm] "5 x 5.8mm:  Panasonic C"
  rect 2.8x1.6 smd: 1(-2.15,0) 2(2.15,0)
  silkscreen extent -2.75,-2.75 2.75,2.75
SMB [mil] "Molded Diode, 2-Leads, Body 5.4x3.6mm, IPC Medium Density, based on OnSemi component dimensions"
  rect 85x107.99 smd: 1(-87.01,0) 2(87.01,0)
  silkscreen extent -155,-82 125,82
SML-P1_GREEN [mm] "ROHM"
  rect 0.5x0.6 smd: 1(-0.45,0) 2(0.45,0)
  silkscreen extent -0.95,-0.3 -0.95,0.3
SOT-23 [mm] "SOT23, 3-Leads, Body 2.9x1.3mm, Pitch 0.95mm, Lead Span 2.5mm, IPC Medium Density"
  rrect50% 1x0.6 smd: 1(-1.2,0.95) 2(-1.2,-0.95) 3(1.2,0)
  silkscreen extent -1.63,-1.5 0.7,1.5
STANDOFF_FAB_0022 [mm] "STANDOFF, 2 POS, THRU"
  round 3.18 hole 3.18 unplated: ""(-6.35,0) ""(6.35,0)
  Keep-Out Layer circle w0.05: c6.35,0 r2.352
  Keep-Out Layer circle w0.05: c-6.35,0 r2.352
  silkscreen extent -11.43,-6.35 11.43,6.35
SW_218-12LPST [mm] "SMD, 24-Leads, Body 16.41x5.8mm, Pitch 1.27mm"
  rrect13% 1.27x0.76 smd: 1(-3.81,6.985) 2(-3.81,5.715) 3(-3.81,4.445) 4(-3.81,3.175) 5(-3.81,1.905) 6(-3.81,0.635) 7(-3.81,-0.635) 8(-3.81,-1.905) 9(-3.81,-3.175) 10(-3.81,-4.445) 11(-3.81,-5.715) 12(-3.81,-6.985) 13(3.81,-6.985) 14(3.81,-5.715) 15(3.81,-4.445) 16(3.81,-3.175) 17(3.81,-1.905) 18(3.81,-0.635) 19(3.81,0.635) 20(3.81,1.905) 21(3.81,3.175) 22(3.81,4.445) 23(3.81,5.715) 24(3.81,6.985)
SW_KMR243GLFG [mm] "SMD, 5-Leads, Body 4.2x2.8mm"
  rrect11% 0.9x1 smd: 1(-2.05,0.8) 2(2.05,0.8) 3(-2.05,-0.8) 4(2.05,-0.8)
  rrect18% 1.7x0.55 smd: 5(0,1.425)
  silkscreen extent -2.2,1.85 -1.79,2.26
TI_Stacked_Overlay_Small [mil]
TLMx1000_Red [mm] "SMD, 2-Leads, Body 1.6x0.8mm"
  rrect17% 0.6x0.8 smd: 1(-0.725,0) 2(0.725,0)
  silkscreen extent -0.97,-0.8 1.6,0.8
TLMx1000_Yellow [mm] "SMD, 2-Leads, Body 1.6x0.8mm"
  rrect17% 0.6x0.8 smd: 1(-0.725,0) 2(0.725,0)
  silkscreen extent -0.97,-0.8 1.6,0.8
TSSOP-8 [mm] "TSSOP, 8-Leads, Body 3.1x4.5mm (max), Pitch 0.65mm, IPC Medium Density"
  rrect50% 1.7x0.35 smd: 1(-2.85,0.975) 2(-2.85,0.325) 3(-2.85,-0.325) 4(-2.85,-0.975) 5(2.85,-0.975) 6(2.85,-0.325) 7(2.85,0.325) 8(2.85,0.975)
  silkscreen extent -4.23,-1.55 1.6,1.55
TSW-102-07-X-S [mm] "Samtec 100 mil 1x2 head, 230 mil above insulator"
  rrect6% 1.65x1.65 hole 1.016: 1(-1.27,0)
  round 1.65 hole 1.016: 2(1.27,0)
  silkscreen extent -3.42,-1.4 2.72,1.4
TSW-105-07-G-D [mm] "Samtec 100mil, 2x5, 230 mil above insulator"
  rrect6% 1.65x1.65 hole 1.016: 1(-5.08,-1.27)
  round 1.65 hole 1.016: 2(-5.08,1.27) 3(-2.54,-1.27) 4(-2.54,1.27) 5(0,-1.27) 6(0,1.27) 7(2.54,-1.27) 8(2.54,1.27) 9(5.08,-1.27) 10(5.08,1.27)
  silkscreen extent -8,-2.54 6.35,2.54
TSW-108-07-G-D [mm] "Samtec 100mil, 2x8, 230 mil above insulator"
  rrect6% 1.65x1.65 hole 1.016: 1(-8.89,-1.27)
  round 1.65 hole 1.016: 2(-8.89,1.27) 3(-6.35,-1.27) 4(-6.35,1.27) 5(-3.81,-1.27) 6(-3.81,1.27) 7(-1.27,-1.27) 8(-1.27,1.27) 9(1.27,-1.27) 10(1.27,1.27) 11(3.81,-1.27) 12(3.81,1.27) 13(6.35,-1.27) 14(6.35,1.27) 15(8.89,-1.27) 16(8.89,1.27)
  silkscreen extent -10.16,-4.24 10.16,2.54
WEEE_Minimum [mil] "WEEElie bin"
  silkscreen extent 22,-71 54,74
XAL5030 [mil] "Coilcraft XAL5030 12/12/11"
  rect 46x183 smd: 1(-65,0) 2(65,0)
  silkscreen extent -108,-112 108,112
